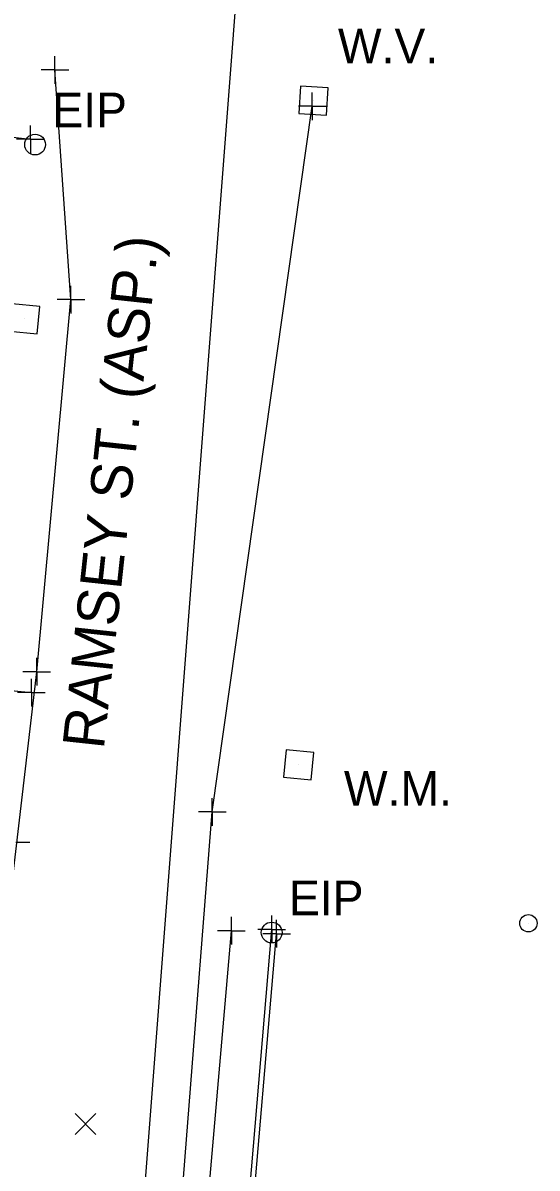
# Model space of a CAD drawing. Extents: x 0 to 1944463, y 0 to 420651.
# Drawn here: x 1943400.2 to 1943474.5, y 417563 to 417728.5 of the extents above; entities that cross this region are included whole.
import ezdxf

# ---------------------------------------------------------------- set-up
doc = ezdxf.new("R2010")
doc.units = 0
for name, color, linetype in [('SUR - DTM - Breaklines', 7, 'Continuous'), ('SUR - DTM - Breaklines - Points - Locators', 7, 'Continuous'), ('SUR - DTM - Spot Points - Locators', 7, 'Continuous'), ('SUR - NON-TRAN - Features', 7, 'Continuous'), ('SUR - NON-TRAN - Features - Points - Locators', 7, 'Continuous'), ('SUR - PROPERTY - Property Lines', 7, 'Continuous'), ('SUR - PROPERTY - Property Markers', 7, 'Continuous'), ('SUR - TRAN - Features', 7, 'Continuous'), ('SUR - TRAN - Features - Points - Locators', 7, 'Continuous'), ('SUR - TRAN - Roads Text', 7, 'Continuous'), ('SUR - UTL - Gas', 7, 'Continuous'), ('SUR - UTL - Gas - Points - Locators', 7, 'Continuous'), ('SUR - UTL - Low Wire Crossings', 7, 'Continuous'), ('SUR - UTL - Sanitary Sewer', 7, 'Continuous'), ('SUR - UTL - Water', 7, 'Continuous'), ('SUR - UTL - Water - Points - Locators', 7, 'Continuous'), ('SUR - UTL - Water Text', 7, 'Continuous')]:
    doc.layers.add(name, color=color, linetype=linetype)

msp = doc.modelspace()

# ---------------------------------------------------------------- linework, layer by layer
at = {"layer": 'SUR - DTM - Breaklines'}
msp.add_lwpolyline([(1943429.16, 417509.05), (1943432.82, 417550.08), (1943436.81, 417596.89)], dxfattribs=at)
at = {"layer": 'SUR - DTM - Breaklines - Points - Locators'}
for q in [(1943436.81, 417598.89), (1943434.81, 417596.89), (1943438.81, 417596.89), (1943436.81, 417594.89)]:
    msp.add_line((1943436.81, 417596.89), q, dxfattribs=at)
at = {"layer": 'SUR - DTM - Spot Points - Locators'}
msp.add_line((1943473.22, 417598.4), (1943473.22, 417598.4), dxfattribs=at)
msp.add_circle((1943473.21, 417598.41), 1.25, dxfattribs=at)
at = {"layer": 'SUR - NON-TRAN - Features'}
for points in [[(1943242.05, 417651.23), (1943255.39, 417693.33), (1943266.15, 417726.25), (1943294.45, 417723.19), (1943361.01, 417716.22), (1943401.26, 417711.69)], [(1943428.5, 417508.78), (1943432.14, 417550.26), (1943436.11, 417597.52)]]:
    msp.add_lwpolyline(points, dxfattribs=at)
at = {"layer": 'SUR - NON-TRAN - Features - Points - Locators'}
for p, q in [((1943401.26, 417711.69), (1943401.26, 417713.69)), ((1943401.26, 417711.69), (1943399.26, 417711.69)), ((1943401.26, 417711.69), (1943403.26, 417711.69)), ((1943401.26, 417711.69), (1943401.26, 417709.69)), ((1943436.11, 417597.52), (1943436.11, 417599.52)), ((1943436.11, 417597.52), (1943434.11, 417597.52)), ((1943436.11, 417597.52), (1943438.11, 417597.52)), ((1943436.11, 417597.52), (1943436.11, 417595.52))]:
    msp.add_line(p, q, dxfattribs=at)
at = {"layer": 'SUR - PROPERTY - Property Lines'}
msp.add_line((1943399.16, 417610.14), (1943401.16, 417610.14), dxfattribs=at)
at = {"layer": 'SUR - PROPERTY - Property Markers'}
for centre in [(1943401.92, 417710.93), (1943436.11, 417597.07)]:
    msp.add_circle(centre, 1.5, dxfattribs=at)
at = {"layer": 'SUR - TRAN - Features'}
for points in [[(1943372.86, 417634.57), (1943401.4, 417631.75)], [(1943417.53, 417451.44), (1943421.08, 417492.41), (1943421.42, 417496.26), (1943422.57, 417508.54), (1943422.97, 417512.47), (1943426.23, 417550.14), (1943430.3, 417597.34)]]:
    msp.add_lwpolyline(points, dxfattribs=at)
at = {"layer": 'SUR - TRAN - Features - Points - Locators'}
for p, q in [((1943401.4, 417631.75), (1943401.4, 417633.75)), ((1943401.4, 417631.75), (1943399.4, 417631.75)), ((1943401.4, 417631.75), (1943403.4, 417631.75)), ((1943401.4, 417631.75), (1943401.4, 417629.75)), ((1943430.3, 417597.34), (1943430.3, 417599.34)), ((1943430.3, 417597.34), (1943428.3, 417597.34)), ((1943430.3, 417597.34), (1943432.3, 417597.34)), ((1943430.3, 417597.34), (1943430.3, 417595.34))]:
    msp.add_line(p, q, dxfattribs=at)
at = {"layer": 'SUR - UTL - Gas'}
msp.add_lwpolyline([(1943395.98, 417582.02), (1943402.17, 417634.75), (1943407.11, 417688.53), (1943404.78, 417721.72)], dxfattribs=at)
at = {"layer": 'SUR - UTL - Gas - Points - Locators'}
for p, q in [((1943404.78, 417721.72), (1943404.78, 417723.72)), ((1943404.78, 417721.72), (1943402.78, 417721.72)), ((1943404.78, 417721.72), (1943406.78, 417721.72)), ((1943404.78, 417721.72), (1943404.78, 417719.72)), ((1943407.11, 417688.53), (1943407.11, 417690.53)), ((1943407.11, 417688.53), (1943405.11, 417688.53)), ((1943407.11, 417688.53), (1943409.11, 417688.53)), ((1943407.11, 417688.53), (1943407.11, 417686.53)), ((1943402.17, 417634.75), (1943402.17, 417636.75)), ((1943402.17, 417634.75), (1943400.17, 417634.75)), ((1943402.17, 417634.75), (1943404.17, 417634.75)), ((1943402.17, 417634.75), (1943402.17, 417632.75))]:
    msp.add_line(p, q, dxfattribs=at)
at = {"layer": 'SUR - UTL - Low Wire Crossings'}
for p, q in [((1943407.71, 417570.9), (1943410.71, 417567.9)), ((1943410.71, 417570.9), (1943407.71, 417567.9)), ((1943409.21, 417569.4), (1943409.21, 417569.4))]:
    msp.add_line(p, q, dxfattribs=at)
at = {"layer": 'SUR - UTL - Sanitary Sewer'}
msp.add_lwpolyline([(1943405.06, 417394.5), (1943437.29, 417814.01)], dxfattribs=at)
at = {"layer": 'SUR - UTL - Water'}
for p, q in [((1943442.13, 417717.27), (1943442.13, 417717.27)), ((1943400.42, 417685.75), (1943400.42, 417685.75)), ((1943440.01, 417621.3), (1943440.01, 417621.3))]:
    msp.add_line(p, q, dxfattribs=at)
for points in [[(1943440.26, 417719.39), (1943440.02, 417715.4), (1943444.01, 417715.16), (1943444.25, 417719.15), (1943440.26, 417719.39)], [(1943407.92, 417397.09), (1943413.86, 417450.48), (1943415.59, 417468.22), (1943420.48, 417524.75), (1943427.53, 417614.49), (1943441.98, 417716.46)], [(1943402.61, 417687.54), (1943398.63, 417687.94), (1943398.23, 417683.96), (1943402.21, 417683.56), (1943402.61, 417687.54)], [(1943438.21, 417623.48), (1943437.83, 417619.5), (1943441.81, 417619.12), (1943442.19, 417623.1), (1943438.21, 417623.48)]]:
    msp.add_lwpolyline(points, dxfattribs=at)
at = {"layer": 'SUR - UTL - Water - Points - Locators'}
for p, q in [((1943441.98, 417716.46), (1943441.98, 417718.46)), ((1943441.98, 417716.46), (1943439.98, 417716.46)), ((1943441.98, 417716.46), (1943443.98, 417716.46)), ((1943441.98, 417716.46), (1943441.98, 417714.46)), ((1943427.53, 417614.49), (1943427.53, 417616.49)), ((1943427.53, 417614.49), (1943425.53, 417614.49)), ((1943427.53, 417614.49), (1943429.53, 417614.49)), ((1943427.53, 417614.49), (1943427.53, 417612.49))]:
    msp.add_line(p, q, dxfattribs=at)

# ---------------------------------------------------------------- texts
at = {"layer": 'SUR - PROPERTY - Property Markers'}
for p in [(1943404.42, 417713.43), (1943438.61, 417599.57)]:
    msp.add_text('EIP', height=5, dxfattribs=at).set_placement(p)
at = {"layer": 'SUR - TRAN - Roads Text'}
msp.add_text('RAMSEY ST. (ASP.)', height=6, rotation=83.8406, dxfattribs=at).set_placement((1943411.84, 417623.44))
at = {"layer": 'SUR - UTL - Water Text'}
for s, p in [('W.V.', (1943445.68, 417722.69)), ('W.M.', (1943446.55, 417615.4))]:
    msp.add_text(s, height=5, dxfattribs=at).set_placement(p)

doc.saveas('drawing.dxf')
